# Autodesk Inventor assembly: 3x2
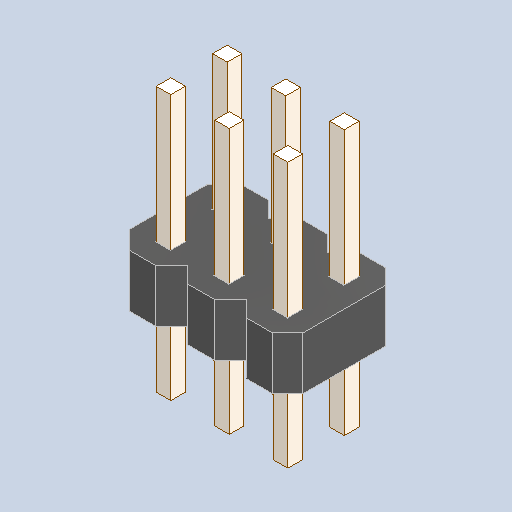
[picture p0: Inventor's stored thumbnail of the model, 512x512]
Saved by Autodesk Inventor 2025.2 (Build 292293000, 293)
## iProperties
Created: 2025-04
Part Number: 3x2
Description: PART--DESC
Document SubType Name: Assembly
Designer: BennF
Author: BennF
Revision Number: NONE
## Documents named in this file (3)
- C:\Users\BennF\Nextcloud\Benutzer\CNC JarBeRi\existing parts\Electronics\RepRap A4988 Shied (USE WITHOUT ARDUINO)\reprap-a4988-1.snapshot.1\RepRap\RepRap\3x2_4.iam
- C:\Users\BennF\Nextcloud\Benutzer\CNC JarBeRi\existing parts\Electronics\RepRap A4988 Shied (USE WITHOUT ARDUINO)\reprap-a4988-1.snapshot.1\RepRap\RepRap\3x2 Geometry.ipt
- C:\Users\BennF\Nextcloud\Benutzer\CNC JarBeRi\existing parts\Electronics\RepRap A4988 Shied (USE WITHOUT ARDUINO)\reprap-a4988-1.snapshot.1\RepRap\RepRap\pin10.ipt
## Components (2 placed, 2 different names)
1. 3x2 Geometry
2. pin10
